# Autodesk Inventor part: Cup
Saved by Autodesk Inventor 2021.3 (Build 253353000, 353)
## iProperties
Created: 2023-03
Part Number: Cup
Material: Generic
Document SubType Name: Modeling
Designer: AdminForWorker
Density: 1 g/cm^3
Appearance: Default
Title: Cup
Author: AdminForWorker
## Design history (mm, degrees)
feature "Body1"
body "Solid1"
